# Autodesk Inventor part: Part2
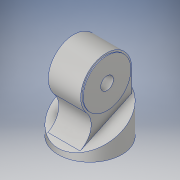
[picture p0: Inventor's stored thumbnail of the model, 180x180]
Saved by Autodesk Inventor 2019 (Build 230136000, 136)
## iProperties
Created: 2018-07
Part Number: Part2
Material: Aluminum 6061
Description: 123456
Document SubType Name: Modeling
Designer: Power User
Mass: 162915 g
Surface Area: 10619 cm^2
Volume: 18450.2 cm^3
Density: 2.7 g/cm^3
Appearance: Aluminum - Flat
Title: GEAR
Author: Power User
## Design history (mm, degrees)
sketch "Sketch6"
  geometry: C1 r 75 at (0, 0); 1 further point
  constraints: 1 centre point, 1 coincident
  dimensions: "d44" = 150 diameter of C1
extrude "Extrusion5" new body sketch "Sketch6" distance "d45" = 100; taper "d46" = 0 deg
sketch "Sketch7"
  geometry: L1 (0, 75)-(0, -75) reference; L2 (0, 102.879)-(99.808, -111.161); L3 (0, 75)-(100, 75) reference; L4 (0, 102.879)-(-29.654, 102.879); L5 (-29.654, 102.879)-(-29.654, -111.161); L6 (-29.654, -111.161)-(99.808, -111.161); 2 further points
  constraints: 8 end point, 3 point on line, 2 perpendicular, 1 horizontal
  dimensions: "d47" = 25 deg angle of L1 L2; "d49" = 13 distance from line of L1 point (13, 75)
extrude "Extrusion6" sketch "Sketch7" stored distance "d50" = 200; taper "d51" = 0 deg
sketch "Sketch8"
  geometry: L1 (82.946, -75)-(13, 75) reference; L2 (128, -60)-(75.952, -60); L3 (13, 75)-(82.946, -75) reference; L4 (82.946, -75)-(0, -75) reference; L5 (0, -75)-(0, 75) reference; L6 (0, 75)-(13, 75) reference; L7 (0, 75)-(0, -75) reference; L8 (19.444, 61.181)-(75.952, -60); C1 r 56 at (128, 0); C2 r 15 at (128, 0); A1 r 60 centre (128, 0) between (128, -60) and (89.273, 45.828); A2 r 45 centre (60.228, 80.199) between (19.444, 61.181) and (89.273, 45.828); 1 further point
  constraints: 4 centre point, 4 end point, 4 point on circle, 3 tangent, 2 coincident, 2 point on line, 1 collinear, 1 horizontal
  dimensions: "d52" = 75 distance from line of L4 C1.centre; "d53" = 120 diameter of A1; "d54" = 112 diameter of C1; "d55" = 128 distance from line of C1.centre L7; "d56" = 45 radius of A2; "d57" = 30 diameter of C2
  node "Project Cut Edges2"
extrude "Extrusion7" join sketch "Sketch8" stored distance "d58" = 76; taper "d59" = 0 deg
extrude "Extrusion8" join sketch "Sketch8" stored distance "d60" = 80; taper "d61" = 0 deg
body "Solid2"
